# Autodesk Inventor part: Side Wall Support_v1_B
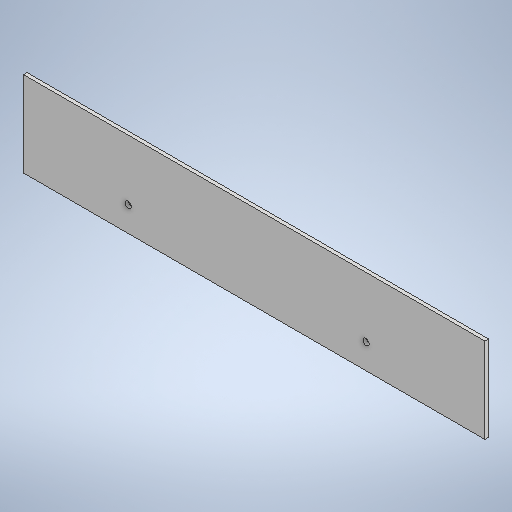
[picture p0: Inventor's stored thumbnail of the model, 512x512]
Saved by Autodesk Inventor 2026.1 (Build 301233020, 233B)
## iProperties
Created: 2026-10
Part Number: Side Wall Support_v1_B
Material: Generic
Document SubType Name: Modeling
Designer: hp
Density: 1 g/cm^3
Appearance: Default
Author: hp
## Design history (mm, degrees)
sketch "Sketch1"
  geometry: L1 (0, 0)-(700, 0); L2 (700, 120)-(0, 120); L3 (0, 120)-(0, 0); L4 (700, 120)-(700, 0); L5 (50, 120)-(50, 0)
  constraints: 10 end point, 2 point on line, 1 horizontal, 1 parallel, 1 perpendicular, 1 vertical
  dimensions: "d28" = 700 distance of L2.start L2.end; "d29" = 120 distance of L2.end L1.start; "d48" = 50 distance between parallel lines of L3 L5
extrude "Extrusion2" new body sketch "Sketch1" distance "d23" = 5; taper "d24" = 0 deg
sketch "Sketch5"
  geometry: 2 further points
hole "Hole2" sketch "Sketch5" at (197.5, 35), (532.5, 35) diameter "d56" = 9; stored, may be unused: countersink angle "d60" = 90 deg, drill point angle "d62" = 0 deg; dims "d57" = 6, "d58" = 4, "d59" = 2, "d61" = 8
body "Solid2"
